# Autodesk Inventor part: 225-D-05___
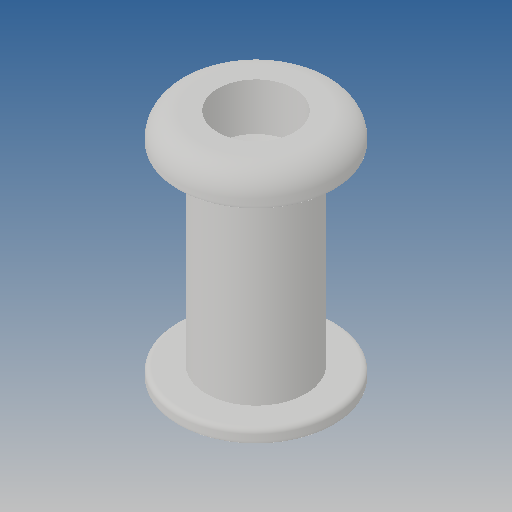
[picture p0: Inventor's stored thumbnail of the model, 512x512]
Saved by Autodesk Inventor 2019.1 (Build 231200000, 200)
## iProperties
Created: 2013-01
Part Number: 225-D-05___
Material: Ogólny
Document SubType Name: Modeling
Designer: CADENGINEERING4
Density: 1 g/cm^3
Appearance: Domyślna
Author: CADENGINEERING4
Revision Number: ÈÎºÎ
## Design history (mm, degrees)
feature "NONE"
node "Bryła1"
